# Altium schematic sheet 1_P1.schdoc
size 525 x 264 mm; Symbol: Sheet-Symbol_A4; Device: Sheet-Symbol_A4; @Project Name: Project Name; @Page Count: 3; @Update Date: 2021.11.05; @Create Date: 2024-10-23; @Schematic Name: Schematic Name; @Page No: 1; @Page Name: P1; Company: EasyEDA.com; Reviewed: NGUYỄN TẤN TÀI; Version: V0.1; Page Size: A4; Part Number: JLCPCB-002; Drawn: NGUYỄN TẤN TÀI; Title Block Position: 3; Width: 2000; Height: 1000; Region Start: 1; X Region Count: 6; Y Region Count: 4; Color: #000000; Blade Width: 10; @Board Name: Board1; @Create Time: 23:51:59; @Update Time: 22:14:05
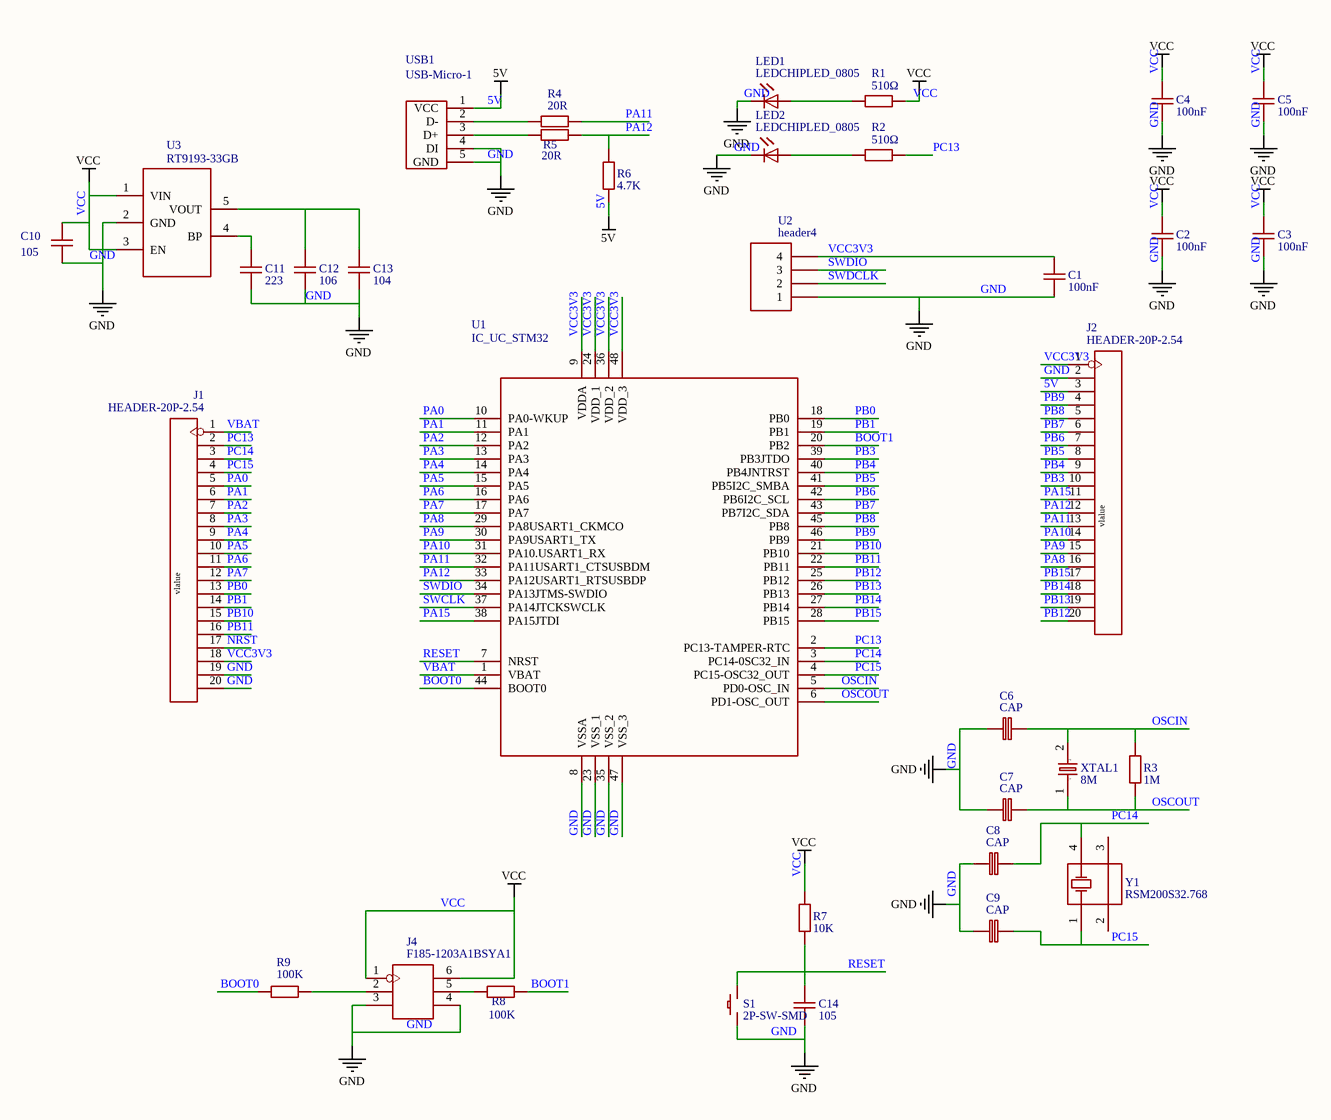
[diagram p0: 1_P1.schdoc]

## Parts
C1  100nF  (value not drawn)
C2  100nF  (value not drawn)
C3  100nF  (value not drawn)
C4  100nF  (value not drawn)
C5  100nF  (value not drawn)
C6  CAP  (value not drawn)
C7  CAP  (value not drawn)
C8  CAP  (value not drawn)
C9  CAP  (value not drawn)
C10  105  (value not drawn)
C11  223  (value not drawn)
C12  106  (value not drawn)
C13  104  (value not drawn)
C14  105  (value not drawn)
J1  HEADER-20P-2.54  (value not drawn)
J2  HEADER-20P-2.54  (value not drawn)
J4  F185-1203A1BSYA1  (value not drawn)
LED1  LEDCHIPLED_0805  (value not drawn)
LED2  LEDCHIPLED_0805  (value not drawn)
R1  510Ω  (value not drawn)
R2  510Ω  (value not drawn)
R3  1M  (value not drawn)
R4  20R  (value not drawn)
R5  20R  (value not drawn)
R6  4.7K  (value not drawn)
R7  10K  (value not drawn)
R8  100K  (value not drawn)
R9  100K  (value not drawn)
S1  2P-SW-SMD  (value not drawn)
U1  IC_UC_STM32  (value not drawn)
U2  header4  (value not drawn)
U3  RT9193-33GB  (value not drawn)
USB1  USB-Micro-1  (value not drawn)
XTAL1  8M  (value not drawn)
Y1  RSM200S32.768  (value not drawn)

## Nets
5V: J2.3(P$3) R6.1 USB1.1(VCC)
GND: C1.1 C2.1 C3.1 C4.1 C5.1 C6.1 C7.1 C8.1 C9.1 C10.2 C11.1 C12.1 C13.1 C14.1 J1.19(P$19) J1.20(P$20) J2.2(P$2) J4.3 J4.4 LED1.C LED2.C S1.2 U1.8(VSSA) U1.23(VSS_1) U1.35(VSS_2) U1.47(VSS_3) U2.1 U3.2(GND) USB1.4(DI) USB1.5(GND)
VCC: C2.2 C3.2 C4.2 C5.2 C10.1 J4.1 J4.6 R1.2 R7.2 U3.1(VIN) U3.3(EN)
BOOT0: R9.2 U1.44(BOOT0)
BOOT1: R8.1 U1.20(PB2)
NRST: J1.17(P$17)
OSCIN: C6.2 R3.2 U1.5(PD0-OSC_IN) XTAL1.2
OSCOUT: C7.2 R3.1 U1.6(PD1-OSC_OUT) XTAL1.1
PA0: J1.5(P$5) U1.10(PA0-WKUP)
PA1: J1.6(P$6) U1.11(PA1)
PA2: J1.7(P$7) U1.12(PA2)
PA3: J1.8(P$8) U1.13(PA3)
PA4: J1.9(P$9) U1.14(PA4)
PA5: J1.10(P$10) U1.15(PA5)
PA6: J1.11(P$11) U1.16(PA6)
PA7: J1.12(P$12) U1.17(PA7)
PA8: J2.16(P$16) U1.29(PA8USART1_CKMCO)
PA9: J2.15(P$15) U1.30(PA9USART1_TX)
PA10: J2.14(P$14) U1.31(PA10.USART1_RX)
PA11: J2.13(P$13) R4.2 U1.32(PA11USART1_CTSUSBDM)
PA12: J2.12(P$12) R5.2 R6.2 U1.33(PA12USART1_RTSUSBDP)
PA15: J2.11(P$11) U1.38(PA15JTDI)
PB0: J1.13(P$13) U1.18(PB0)
PB1: J1.14(P$14) U1.19(PB1)
PB3: J2.10(P$10) U1.39(PB3JTDO)
PB4: J2.9(P$9) U1.40(PB4JNTRST)
PB5: J2.8(P$8) U1.41(PB5I2C_SMBA)
PB6: J2.7(P$7) U1.42(PB6I2C_SCL)
PB7: J2.6(P$6) U1.43(PB7I2C_SDA)
PB8: J2.5(P$5) U1.45(PB8)
PB9: J2.4(P$4) U1.46(PB9)
PB10: J1.15(P$15) U1.21(PB10)
PB11: J1.16(P$16) U1.22(PB11)
PB12: J2.20(P$20) U1.25(PB12)
PB13: J2.19(P$19) U1.26(PB13)
PB14: J2.18(P$18) U1.27(PB14)
PB15: J2.17(P$17) U1.28(PB15)
PC13: J1.2(P$2) R2.2 U1.2(PC13-TAMPER-RTC)
PC14: C8.2 J1.3(P$3) U1.3(PC14-0SC32_IN) Y1.4(OSC2)
PC15: C9.2 J1.4(P$4) U1.4(PC15-OSC32_OUT) Y1.1(OSC1)
RESET: C14.2 R7.1 S1.3 U1.7(NRST)
SWCLK: U1.37(PA14JTCKSWCLK)
SWDCLK: U2.2
SWDIO: U1.34(PA13JTMS-SWDIO) U2.3
VBAT: J1.1(P$1) U1.1(VBAT)
VCC3V3: C1.2 J1.18(P$18) J2.1(P$1) U1.9(VDDA) U1.24(VDD_1) U1.36(VDD_2) U1.48(VDD_3) U2.4
NetC11_2: C11.2 U3.4(BP)
NetC12_2: C12.2 C13.2 U3.5(VOUT)
NetJ4_2: J4.2 R9.1
NetJ4_5: J4.5 R8.2
NetLED1_A: LED1.A R1.1
NetLED2_A: LED2.A R2.1
NetR4_1: R4.1 USB1.2(D-)
NetR5_1: R5.1 USB1.3(D+)

Not connected (* = marked no-connect by the designer): Y1 2(COM) 3(COM)

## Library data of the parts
C1-C5 = 100nF: Manufacturer: FH; Manufacturer Part: 0603B104K500NT; Voltage: 50V; Tolerance: ±10%; EasyEDA: E30926; Convert to PCB: yes; Origin Footprint: 0603
C6-C9 = CAP: Convert to PCB: yes; Origin Footprint: 0603-CAP
C10 = 105: Manufacturer: FH; Manufacturer Part: 0603B105K250NT; Value: 1uF; Voltage: 25V; Tolerance: ±10%; EasyEDA: E59302; Convert to PCB: yes; Origin Footprint: 0603
C11 = 223: Manufacturer: FH; Manufacturer Part: 0603B104K500NT; Value: 100nF; Voltage: 50V; Tolerance: ±10%; EasyEDA: E30926; Convert to PCB: yes; Origin Footprint: 0603
C12 = 106: Manufacturer: FH; Manufacturer Part: 0603B104K500NT; Value: 100nF; Voltage: 50V; Tolerance: ±10%; EasyEDA: E30926; Convert to PCB: yes; Origin Footprint: 0603
C13 = 104: Manufacturer: FH; Manufacturer Part: 0603B104K500NT; Value: 100nF; Voltage: 50V; Tolerance: ±10%; EasyEDA: E30926; Convert to PCB: yes; Origin Footprint: 0603
C14 = 105: Manufacturer: FH; Manufacturer Part: 0603B104K500NT; Value: 100nF; Voltage: 50V; Tolerance: ±10%; EasyEDA: E30926; Convert to PCB: yes; Origin Footprint: 0603
J1 J2 = HEADER-20P-2.54: Convert to PCB: yes; Origin Footprint: H20-2.54
J4 = F185-1203A1BSYA1: SeeedStudio: 320030011; Convert to PCB: yes; Origin Footprint: H2X3-2.54
LED1 LED2 = LEDCHIPLED_0805: Convert to PCB: yes
R1 R2 = 510Ω: Manufacturer: UniOhm; Manufacturer Part: 0603WAF5100T5E; Power: 1/10W; Tolerance: ±1%; EasyEDA: E23193; Convert to PCB: yes; Origin Footprint: 0603
R3 = 1M: Manufacturer: UniOhm; Manufacturer Part: 0603WAF5100T5E; Power: 1/10W; Value: 510Ω; Tolerance: ±1%; EasyEDA: E23193; Convert to PCB: yes; Origin Footprint: 0603
R4 R5 = 20R: Manufacturer: UniOhm; Manufacturer Part: 0603WAF5100T5E; Power: 1/10W; Value: 510Ω; Tolerance: ±1%; EasyEDA: E23193; Convert to PCB: yes; Origin Footprint: 0603
R6 = 4.7K: Manufacturer: UniOhm; Manufacturer Part: 0603WAF5100T5E; Power: 1/10W; Value: 510Ω; Tolerance: ±1%; EasyEDA: E23193; Convert to PCB: yes; Origin Footprint: 0603
R7 = 10K: Manufacturer: UniOhm; Manufacturer Part: 0603WAF5100T5E; Power: 1/10W; Value: 510Ω; Tolerance: ±1%; EasyEDA: E23193; Convert to PCB: yes; Origin Footprint: 0603
R8 R9 = 100K: Manufacturer: UniOhm; Manufacturer Part: 0603WAF5100T5E; Power: 1/10W; Value: 510Ω; Tolerance: ±1%; EasyEDA: E23193; Convert to PCB: yes; Origin Footprint: 0603
S1 = 2P-SW-SMD: Convert to PCB: yes; Origin Footprint: 2PSW-SMD
U1 = IC_UC_STM32: Convert to PCB: yes; Origin Footprint: LQFP48
U2 = header4: Convert to PCB: yes; Origin Footprint: H4-2.54
U3 = RT9193-33GB: Manufacturer: RICHTEK; EasyEDA: E15651; Convert to PCB: yes; Origin Footprint: SOT-23-5
USB1 = USB-Micro-1: Manufacturer: EasyEDA; EasyEDA: E40939; Convert to PCB: yes; Origin Footprint: MICROUSB
XTAL1 = 8M: Convert to PCB: yes; Origin Footprint: HC-49U
Y1 = RSM200S32.768: Convert to PCB: yes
